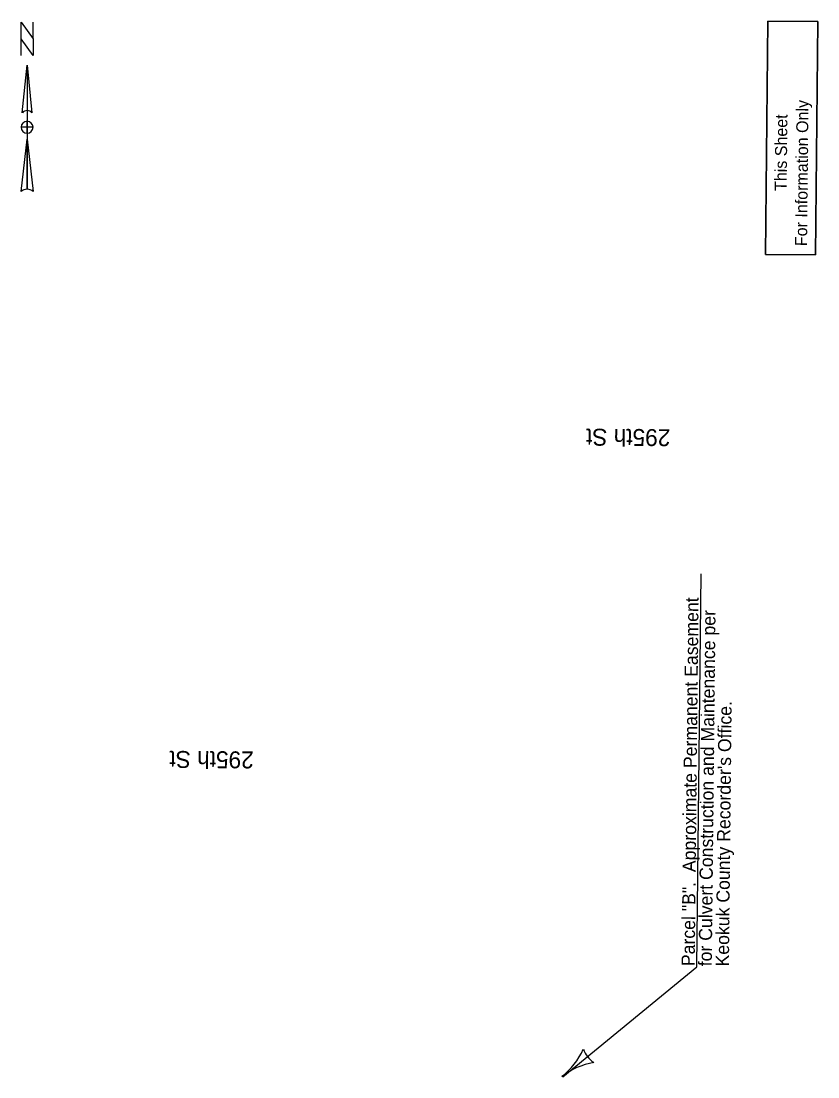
# Model space of a CAD drawing. Extents: x 23417754 to 23421386, y 6737896 to 6790956.
# Drawn here: x 23417789 to 23418731, y 6754688 to 6755936 of the extents above; entities that cross this region are included whole.
import ezdxf

# ---------------------------------------------------------------- set-up
doc = ezdxf.new("R2010")
doc.units = 0
for name, color, linetype in [('Curb', 7, 'Continuous'), ('dsnCellElements', 7, 'Continuous'), ('RasterAttachment', 7, 'Continuous')]:
    doc.layers.add(name, color=color, linetype=linetype)

msp = doc.modelspace()

# ---------------------------------------------------------------- linework, layer by layer
at = {"layer": 'Curb'}
for p, q in [((23417796.4, 6755884), (23417802, 6755827.6)), ((23417796.4, 6755884), (23417796.4, 6755737.5)), ((23417790.7, 6755827.6), (23417790.7, 6755827.6)), ((23417791, 6755828.2), (23417792, 6755829.3)), ((23417796.4, 6755803.7), (23417796.4, 6755803.7)), ((23417789.3, 6755734.7), (23417796.4, 6755796.7))]:
    msp.add_line(p, q, dxfattribs=at)
for points in [[(23417803.4, 6755895.3), (23417789.3, 6755915), (23417789.3, 6755934.7), (23417803.4, 6755915)], [(23418668.6, 6755660.5), (23418671.5, 6755936.1), (23418730.5, 6755935.5), (23418727.6, 6755659.9)], [(23418727.6, 6755659.9), (23418730.5, 6755935.5), (23418671.5, 6755936.1), (23418668.6, 6755660.5)]]:
    msp.add_lwpolyline(points, close=True, dxfattribs=at)
for points in [[(23417789.3, 6755895.3), (23417789.3, 6755934.7), (23417803.4, 6755915), (23417803.4, 6755934.7)], [(23417790.7, 6755827.6), (23417796.4, 6755884), (23417796.4, 6755830.5)], [(23417803.4, 6755810.7), (23417796.4, 6755810.7), (23417796.4, 6755817.8)], [(23417796.4, 6755803.7), (23417796.4, 6755810.7), (23417789.3, 6755810.7)], [(23417796.4, 6755737.5), (23417796.4, 6755796.7), (23417803.4, 6755734.7)]]:
    msp.add_lwpolyline(points, dxfattribs=at)
for centre, radius, start, end in [((23417796.4, 6755823.4), 7.04, 90.0204, 143.1257), ((23417796.4, 6755823.4), 7.04, 36.8481, 90.0218), ((23417796.4, 6755810.7), 7.04, 90, 180), ((23417796.4, 6755810.7), 7.04, 0, 90), ((23417796.4, 6755810.7), 7.04, 180, 270), ((23417796.4, 6755810.7), 7.04, 270, 360), ((23417796.4, 6755727.3), 10.2, 89.9894, 133.619), ((23417796.4, 6755727.3), 10.2, 46.4021, 90.0006)]:
    msp.add_arc(centre, radius, start, end, dxfattribs=at)
at = {"layer": 'dsnCellElements'}
msp.add_lwpolyline([(23418429.3, 6754688.5), (23418587.6, 6754818.4), (23418592.5, 6755282.9)], dxfattribs=at)
for centre, radius, start, end in [((23418375.8, 6754756), 85, 307.7939, 335.8664), ((23418484.3, 6754732.5), 32.8, 200.0605, 235.5272), ((23418480.1, 6754621.6), 85, 99.7214, 127.7939)]:
    msp.add_arc(centre, radius, start, end, dxfattribs=at)

# ---------------------------------------------------------------- texts
at = {"layer": 'Curb'}
for s, height, p in [('For Information Only', 14.174, (23418717.7, 6755670.1)), ('This Sheet', 14.17, (23418693.6, 6755735.3))]:
    msp.add_text(s, height=height, rotation=89.3974, dxfattribs=at).set_placement(p)
at = {"layer": 'dsnCellElements'}
for s, p in [('Parcel "B".  Approximate Permanent Easement', (23418585, 6754819.3)), ('for Culvert Construction and Maintenance per', (23418605.2, 6754819.1)), ("Keokuk County Recorder's Office.", (23418625.4, 6754818.9))]:
    msp.add_text(s, height=15.605, rotation=89.3974, dxfattribs=at).set_placement(p)
at = {"layer": 'RasterAttachment'}
for p in [(23418556.3, 6755453.8), (23418064.2, 6755073)]:
    msp.add_text('295th St', height=20, rotation=179.5786, dxfattribs=at).set_placement(p)

doc.saveas('drawing.dxf')
